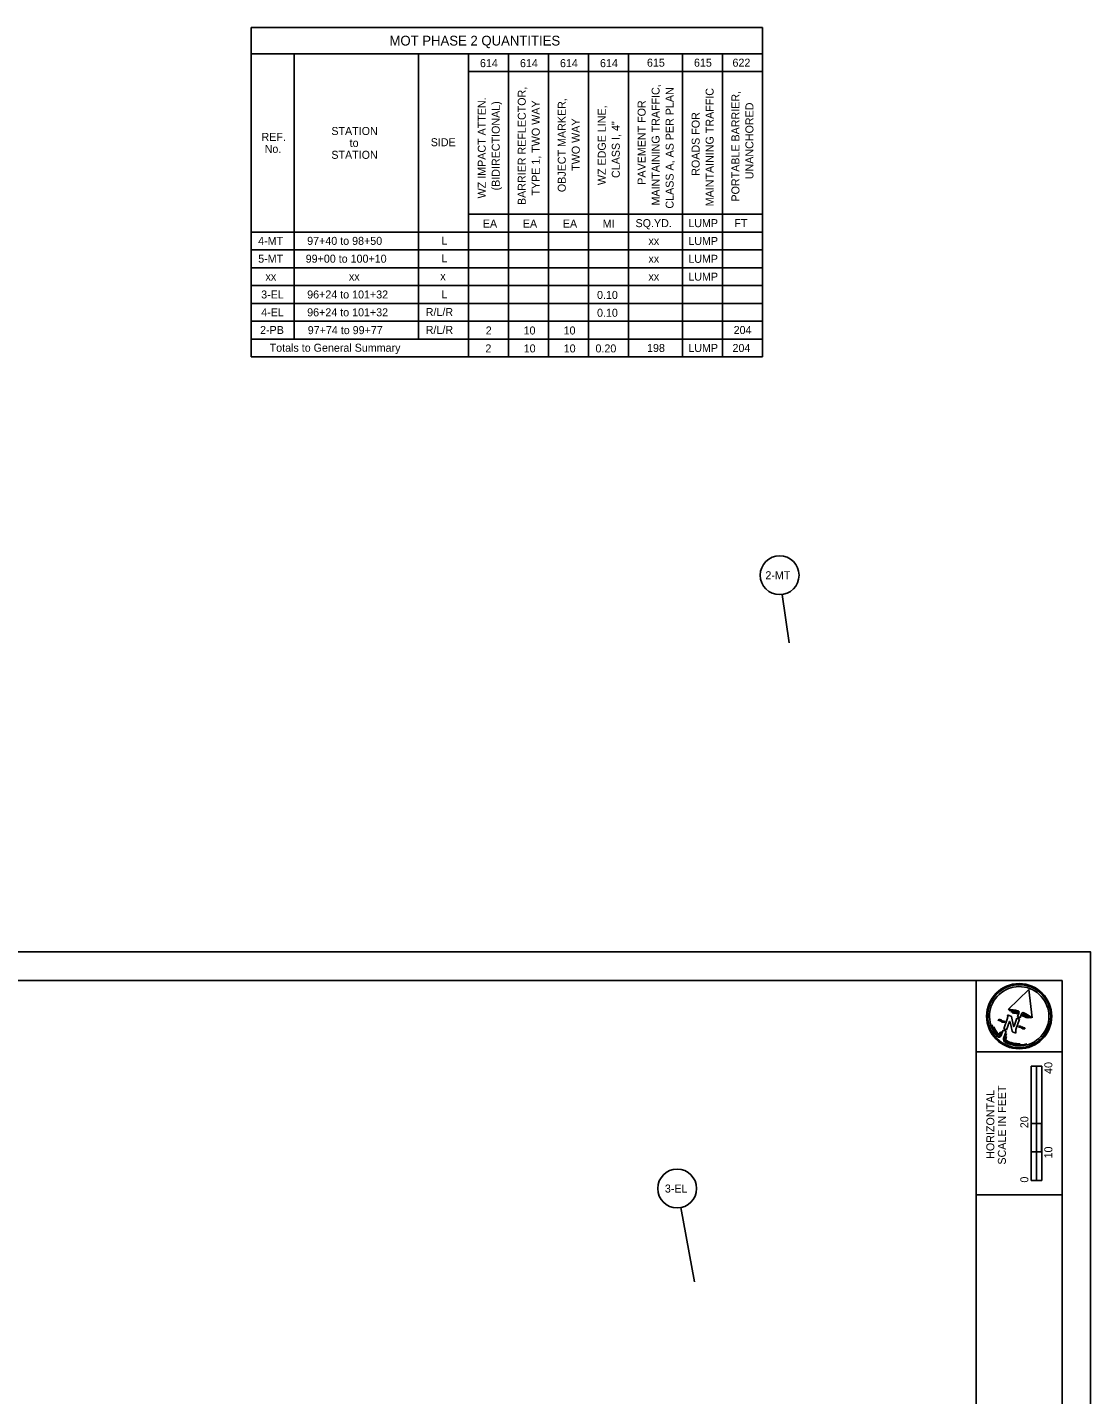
# Model space of a CAD drawing. Extents: x -8.7 to 76.9, y -12.1 to 38.2.
# Drawn here: x 15.4 to 34, y 14.25 to 38.18 of the extents above; entities that cross this region are included whole.
import ezdxf

# ---------------------------------------------------------------- set-up
doc = ezdxf.new("R2010")
doc.units = 0
for name, color, linetype in [('DR_P_Drive_Pipe', 7, 'Continuous'), ('Level 1', 7, 'Continuous'), ('SH_Border', 7, 'Continuous'), ('SH_Cut_Line', 7, 'Continuous'), ('SH_Data', 7, 'Continuous'), ('SH_Text', 7, 'Continuous'), ('TX_P_20', 7, 'Continuous')]:
    doc.layers.add(name, color=color, linetype=linetype)

msp = doc.modelspace()

# ---------------------------------------------------------------- linework, layer by layer
at = {"layer": 'DR_P_Drive_Pipe'}
for centre in [(28.558, 28.592), (26.766, 17.86)]:
    msp.add_circle(centre, 0.34, dxfattribs=at)
at = {"layer": 'Level 1'}
for p, q in [((32.558, 20.994), (32.917, 21.343)), ((32.917, 21.343), (32.974, 20.846)), ((32.48, 20.657), (32.545, 20.84)), ((32.546, 20.899), (32.605, 20.878)), ((32.613, 20.868), (32.648, 20.7)), ((32.66, 20.699), (32.71, 20.84)), ((32.758, 20.823), (32.693, 20.641)), ((32.71, 20.84), (32.758, 20.823)), ((32.72, 20.864), (32.746, 20.93)), ((32.766, 20.847), (32.72, 20.864)), ((32.75, 20.875), (32.75, 20.875)), ((32.75, 20.875), (32.75, 20.875)), ((32.75, 20.875), (32.75, 20.875)), ((32.75, 20.875), (32.75, 20.875)), ((32.383, 20.813), (32.392, 20.796)), ((32.415, 20.594), (32.396, 20.549)), ((32.44, 20.607), (32.41, 20.533)), ((32.471, 20.633), (32.427, 20.525)), ((32.52, 20.616), (32.471, 20.633)), ((32.478, 20.488), (32.52, 20.616)), ((32.528, 20.64), (32.48, 20.657)), ((32.496, 20.771), (32.493, 20.789)), ((32.578, 20.781), (32.528, 20.64)), ((32.625, 20.612), (32.59, 20.78)), ((32.692, 20.581), (32.633, 20.602)), ((32.737, 20.698), (32.745, 20.681)), ((32.85, 20.655), (32.847, 20.674)), ((32.526, 20.575), (32.497, 20.485)), ((32.528, 20.521), (32.514, 20.479))]:
    msp.add_line(p, q, dxfattribs=at)
for radius in [0.57, 0.551]:
    msp.add_circle((32.75, 20.875), radius, dxfattribs=at)
for centre, radius, start, end in [((32.75, 20.875), 0.519, 242.3175, 223.8015), ((32.405, 20.769), 0.0492, 46.1739, 117.1464), ((32.399, 20.872), 0.15, 347.3819, 10.2493), ((32.557, 20.334), 0.66, 75.2449, 89.9278), ((32.557, 20.334), 0.641, 74.1189, 88.4797), ((32.557, 20.334), 0.622, 74.1189, 85.8774), ((32.601, 20.866), 0.0125, 11.628, 70.3807), ((32.557, 20.334), 0.604, 74.1189, 83.1383), ((32.717, 20.942), 0.0312, 338.1603, 75.2449), ((46.471, 16.603), 14.347, 162.5044, 162.7927), ((32.817, 20.907), 0.0313, 65.5761, 162.5044), ((32.557, 20.334), 0.604, 57.6231, 66.6421), ((32.557, 20.334), 0.622, 54.8839, 66.6421), ((32.557, 20.334), 0.641, 52.2817, 66.6421), ((32.557, 20.334), 0.66, 50.8333, 65.5761), ((32.75, 20.875), 0.5, 197.6559, 223.8014), ((32.75, 20.875), 0.481, 202.947, 222.6749), ((32.405, 20.769), 0.0304, 46.1739, 117.1464), ((32.482, 20.851), 0.0818, 227.5765, 279.8651), ((32.482, 20.851), 0.063, 227.5765, 279.8651), ((32.584, 20.779), 0.00625, 11.6269, 160.3807), ((32.637, 20.614), 0.0125, 191.628, 250.3807), ((32.654, 20.701), 0.00625, 191.6269, 340.3807), ((32.839, 20.608), 0.15, 167.3819, 190.2493), ((32.759, 20.654), 0.0492, 46.1739, 117.1464), ((32.759, 20.654), 0.0304, 46.1739, 117.1464), ((32.836, 20.736), 0.0818, 227.5765, 279.8651), ((32.836, 20.736), 0.063, 227.5765, 279.8651), ((32.398, 20.538), 0.0312, 223.8015, 336.6458), ((32.398, 20.538), 0.0125, 223.8014, 337.6936), ((32.538, 20.471), 0.0625, 164.187, 242.3175), ((32.538, 20.471), 0.0438, 162.0193, 242.3217), ((32.538, 20.471), 0.025, 162.018, 242.32), ((32.75, 20.875), 0.5, 242.3217, 285.1975), ((32.75, 20.875), 0.481, 242.32, 271.6975)]:
    msp.add_arc(centre, radius, start, end, dxfattribs=at)
at = {"layer": 'SH_Border'}
for p, q in [((32, 0.5), (32, 21.5)), ((32, 20.25), (33.5, 20.25)), ((32, 17.75), (33.5, 17.75))]:
    msp.add_line(p, q, dxfattribs=at)
msp.add_lwpolyline([(1.5, 21.5), (33.5, 21.5), (33.5, 0.5), (1.5, 0.5)], close=True, dxfattribs=at)
at = {"layer": 'SH_Cut_Line'}
msp.add_lwpolyline([(0, 0), (34, 0), (34, 22), (0, 22)], close=True, dxfattribs=at)
at = {"layer": 'SH_Data'}
for p, q in [((19.313, 38.179), (19.313, 32.413)), ((28.258, 38.179), (19.313, 38.179)), ((28.258, 38.179), (28.258, 32.413)), ((28.258, 37.717), (19.313, 37.717)), ((20.063, 37.717), (20.063, 32.725)), ((22.238, 37.717), (22.238, 32.725)), ((23.113, 37.717), (23.113, 32.413)), ((23.813, 37.717), (23.813, 32.413)), ((24.513, 37.717), (24.513, 32.413)), ((25.213, 37.717), (25.213, 32.413)), ((25.913, 37.717), (25.913, 32.413)), ((26.858, 37.717), (26.858, 32.413)), ((27.558, 37.717), (27.558, 32.413)), ((28.258, 37.405), (23.113, 37.405)), ((28.258, 34.909), (23.113, 34.909)), ((28.258, 34.597), (19.313, 34.597)), ((28.258, 34.285), (19.313, 34.285)), ((28.258, 33.973), (19.313, 33.973)), ((28.258, 33.661), (19.313, 33.661)), ((28.258, 33.349), (19.313, 33.349)), ((28.258, 33.037), (19.313, 33.037)), ((28.258, 32.725), (19.313, 32.725)), ((28.258, 32.413), (19.313, 32.413)), ((32.75, 20.875), (32.75, 20.875)), ((32.957, 18), (32.957, 20)), ((33.144, 20), (32.957, 20)), ((32.957, 19), (32.957, 20)), ((32.957, 20), (33.05, 20)), ((33.05, 20), (33.051, 20)), ((33.051, 20), (33.051, 19)), ((33.144, 20), (33.144, 18)), ((33.051, 19), (32.957, 19)), ((33.143, 19), (33.05, 19)), ((33.05, 19), (33.05, 18.5)), ((33.143, 18.5), (33.143, 19)), ((33.05, 18.5), (32.957, 18.5)), ((32.957, 18.5), (32.957, 18)), ((33.05, 18), (33.05, 18.5)), ((33.05, 18.5), (33.143, 18.5)), ((33.144, 18), (32.957, 18)), ((32.957, 18), (33.05, 18))]:
    msp.add_line(p, q, dxfattribs=at)
at = {"layer": 'TX_P_20'}
for p, q in [((28.605, 28.256), (28.726, 27.408)), ((26.828, 17.526), (27.072, 16.228))]:
    msp.add_line(p, q, dxfattribs=at)

# ---------------------------------------------------------------- texts
at = {"layer": 'DR_P_Drive_Pipe'}
for s, p in [('2-MT', (28.31, 28.522)), ('3-EL', (26.551, 17.79))]:
    msp.add_text(s, height=0.14, rotation=360, dxfattribs=at).set_placement(p)
at = {"layer": 'SH_Data'}
for s, height, rotation, p in [('MOT PHASE 2 QUANTITIES', 0.17175, 360, (21.733, 37.861)), ('40', 0.14, 90, (33.33, 19.866)), ('SCALE IN FEET', 0.14, 90, (32.517, 18.279)), ('HORIZONTAL', 0.14, 90, (32.315, 18.38)), ('20', 0.14, 90, (32.91, 18.916)), ('10', 0.14, 90, (33.33, 18.387)), ('0', 0.14, 90, (32.91, 17.964))]:
    msp.add_text(s, height=height, rotation=rotation, dxfattribs=at).set_placement(p)
at = {"layer": 'SH_Text'}
for s, rotation, p in [('614', 360, (23.316, 37.483)), ('614', 360, (24.016, 37.483)), ('614', 360, (24.716, 37.483)), ('614', 360, (25.416, 37.483)), ('615', 360, (26.237, 37.491)), ('615', 360, (27.06, 37.491)), ('622', 360, (27.734, 37.491)), ('BARRIER REFLECTOR,', 90, (24.117, 35.07)), ('MAINTAINING TRAFFIC,', 90, (26.459, 35.062)), ('CLASS A, AS PER PLAN', 90, (26.704, 35.008)), ('MAINTAINING TRAFFIC', 90, (27.404, 35.048)), ('WZ IMPACT ATTEN.', 90, (23.417, 35.186)), ('(BIDIRECTIONAL)', 90, (23.662, 35.326)), ('TYPE 1, TWO WAY', 90, (24.362, 35.236)), ('OBJECT MARKER,', 90, (24.817, 35.296)), ('PAVEMENT FOR', 90, (26.214, 35.425)), ('PORTABLE BARRIER,', 90, (27.855, 35.131)), ('UNANCHORED', 90, (28.1, 35.522)), ('WZ EDGE LINE,', 90, (25.517, 35.419)), ('ROADS FOR', 90, (27.159, 35.582)), ('STATION', 360, (20.716, 36.296)), ('TWO WAY', 90, (25.062, 35.669)), ('CLASS I, 4"', 90, (25.762, 35.543)), ('REF.', 360, (19.494, 36.192)), ('to', 360, (21.036, 36.087)), ('SIDE', 360, (22.454, 36.099)), ('No.', 360, (19.549, 35.983)), ('STATION', 360, (20.716, 35.879)), ('EA', 360, (23.366, 34.675)), ('EA', 360, (24.066, 34.675)), ('EA', 360, (24.766, 34.675)), ('MI', 360, (25.462, 34.675)), ('SQ.YD.', 360, (26.038, 34.683)), ('LUMP', 360, (26.961, 34.683)), ('FT', 360, (27.767, 34.683)), ('4-MT', 360, (19.435, 34.373)), ('97+40 to 98+50', 360, (20.293, 34.373)), ('L', 360, (22.64, 34.379)), ('xx', 360, (26.264, 34.373)), ('LUMP', 360, (26.961, 34.371)), ('5-MT', 360, (19.436, 34.061)), ('99+00 to 100+10', 360, (20.267, 34.061)), ('L', 360, (22.64, 34.067)), ('xx', 360, (26.264, 34.061)), ('LUMP', 360, (26.961, 34.059)), ('xx', 360, (19.564, 33.749)), ('xx', 360, (21.023, 33.749)), ('x', 360, (22.622, 33.755)), ('xx', 360, (26.264, 33.749)), ('LUMP', 360, (26.961, 33.747)), ('3-EL', 360, (19.488, 33.435)), ('96+24 to 101+32', 360, (20.293, 33.435)), ('L', 360, (22.64, 33.44)), ('0.10', 360, (25.364, 33.427)), ('4-EL', 360, (19.489, 33.123)), ('96+24 to 101+32', 360, (20.293, 33.123)), ('R/L/R', 360, (22.367, 33.128)), ('0.10', 360, (25.364, 33.115)), ('2-PB', 360, (19.469, 32.813)), ('97+74 to 99+77', 360, (20.303, 32.811)), ('R/L/R', 360, (22.367, 32.816)), ('2', 360, (23.417, 32.805)), ('10', 360, (24.079, 32.805)), ('10', 360, (24.779, 32.805)), ('204', 360, (27.754, 32.813)), ('Totals to General Summary', 360, (19.636, 32.503)), ('2', 360, (23.411, 32.491)), ('10', 360, (24.081, 32.491)), ('10', 360, (24.781, 32.491)), ('0.20', 360, (25.337, 32.491)), ('198', 360, (26.239, 32.499)), ('LUMP', 360, (26.961, 32.499)), ('204', 360, (27.734, 32.499))]:
    msp.add_text(s, height=0.14, rotation=rotation, dxfattribs=at).set_placement(p)

doc.saveas('drawing.dxf')
